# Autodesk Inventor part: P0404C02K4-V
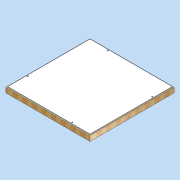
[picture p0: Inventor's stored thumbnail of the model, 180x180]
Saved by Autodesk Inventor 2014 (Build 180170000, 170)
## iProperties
Created: 2011-04
Part Number: P0404C02K4-V
Document SubType Name: Modeling
Designer: david.appleford
Density: 0.21017 g/cm^3
Description: 1w x 1w 02 Ceiling Panel - 4 Locks
Mass: 23000 g
Surface Area: 30294.8 cm^2
Volume: 109435 cm^3
Cost Center: £83.00
Material: Generic
Appearance: Wood (Pine)
Justset: False
Author: david.appleford
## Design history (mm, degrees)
sketch "Sketch1"
  geometry: L1 (0, 0)-(1220, 0); L2 (1220, 0)-(1220, 1220); L3 (1220, 1220)-(0, 1220); L4 (0, 1220)-(0, 0); L5 (34, 1186)-(1186, 1186); L6 (1186, 1186)-(1186, 34); L7 (1186, 34)-(34, 34); L8 (34, 34)-(34, 1186)
  constraints: 16 end point, 4 parallel, 2 perpendicular, 1 horizontal, 3 other
  dimensions: "d0" = 1220 distance between parallel lines of L2 L4 (= w); "d1" = 1220 distance between parallel lines of L1 L3 (= w); "d2" = 34 distance between parallel lines of L5 L3 (= 0.5 x t)
extrude "Extrusion1" new body sketch "Sketch1" distance "d3" = 68 (= t); taper "d4" = 0 deg
sketch "Sketch2"
  geometry: L1 (1186, 1186)-(1186, 34) reference; L2 (34, 1186)-(1186, 1186) reference; L3 (34, 34)-(34, 1186) reference; L4 (1186, 34)-(34, 34) reference; L5 (1176, 1176)-(1176, 44); L6 (1176, 44)-(44, 44); L7 (44, 44)-(44, 1176); L8 (44, 1176)-(1176, 1176); 1 further point
  constraints: 8 end point, 3 other
  dimensions: "d5" = 10 distance between parallel lines of L8 L2
extrude "Extrusion2" join sketch "Sketch2" distance "d6" = 9; taper "d7" = 0 deg
sketch "Sketch3"
  geometry: L1 (-44, 1176)-(-1176, 1176) reference; L2 (-1176, 1176)-(-1176, 44) reference; L3 (-44, 44)-(-44, 1176) reference; L4 (-1176, 44)-(-44, 44) reference; 1 further point
extrude "Extrusion3" join sketch "Sketch3" distance "d8" = 6 (= sw); taper "d9" = 0 deg
sketch "Sketch4"
  geometry: L1 (34, 1186)-(1186, 1186) reference; L2 (1186, 1186)-(1186, 34) reference; L3 (1186, 34)-(34, 34) reference; L4 (34, 34)-(34, 1186) reference; 5 further points
  dimensions: "d10" = 28 distance from line of point (305, 1158) L1 (= k); "d12" = 28 distance from line of L3 point (915, 62) (= k); "d13" = 28 distance from line of point (62, 305) L4 (= k); "d14" = 305 horizontal distance of point (305, 1158) point (0, 0) (= 0.25 x w); "d15" = 610 horizontal distance of point (915, 62) point (305, 1158) (= 0.5 x w); "d16" = 305 vertical distance of point (62, 305) point (0, 0) (= 0.25 x w); "d19" = 610 vertical distance of point (1158, 915) point (62, 305) (= 0.5 x w)
hole "Hole1" sketch "Sketch4" at (305, 1158), (62, 305), (1158, 915), (915, 62) diameter "d22" = 16.3; stored, may be unused: countersink angle "d26" = 90 deg, drill point angle "d28" = 118 deg; dims "d23" = 6, "d24" = 4, "d25" = 2, "d27" = 9
chamfer "Chamfer1" distance "d29" = 3; stored, may be unused: second distance "d30" = 2, angle "d31" = 45 deg
body "Solid1"
node "Projected Loop1"
other parameters: "w" = 1220 [user parameter; used in 6 equation terms], "t" = 68 [user parameter; used in 2 equation terms], "e" = 16 [user parameter], "sw" = 6 [user parameter; used in 1 equation term], "sc" = 9 [user parameter], "sf" = 12 [user parameter], "k" = 28 [user parameter; used in 3 equation terms], "hd" = 12 [user parameter]
